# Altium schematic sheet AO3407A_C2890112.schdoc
size 127 x 101 mm
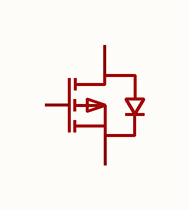
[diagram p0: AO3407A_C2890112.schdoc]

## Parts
Q?  ao3407a  [SOT-23-3_L2.9-W1.3-P1.90-LS2.4-BR]  (value not drawn)

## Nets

Not connected (* = marked no-connect by the designer): Q? 1(G) 2(S) 3(D)

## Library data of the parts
Q? = ao3407a: 数量:1个P沟道;漏源电压(Vdss):30V;连续漏极电流(Id):4.1A;导通电阻(RDS(on)):85mΩ@4.5V;耗散功率(Pd):1.51W;阈值电压(Vgs(th)):2.5V;; Manufacturer: TECH PUBLIC(台舟); Symbol: AO3407A_C2890112; AddInBom: yes; ModelId: c62791f0466c4ae2a892c056b845b0ca; ModelName: SOT-23-3P_L2.9-W1.3-H1.0-LS2.4-P0.95; ModelTransform: 98.425,114.173,0,180,0,0,0.0005,-0.0005,0; Number: 1个P沟道; Drain to Source Voltage: 30V; Current - Continuous Drain(Id): 4.1A; Pd - Power Dissipation: 1.51W; Gate Threshold Voltage (Vgs(th)): 2.5V; Gate Charge(Qg): 6.8nC; Input Capacitance(Ciss): 580pF; Reverse Transfer Capacitance (Crss@Vds): 74pF; Type: P沟道; Output Capacitance(Coss): 98pF; Vgs: ±20V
